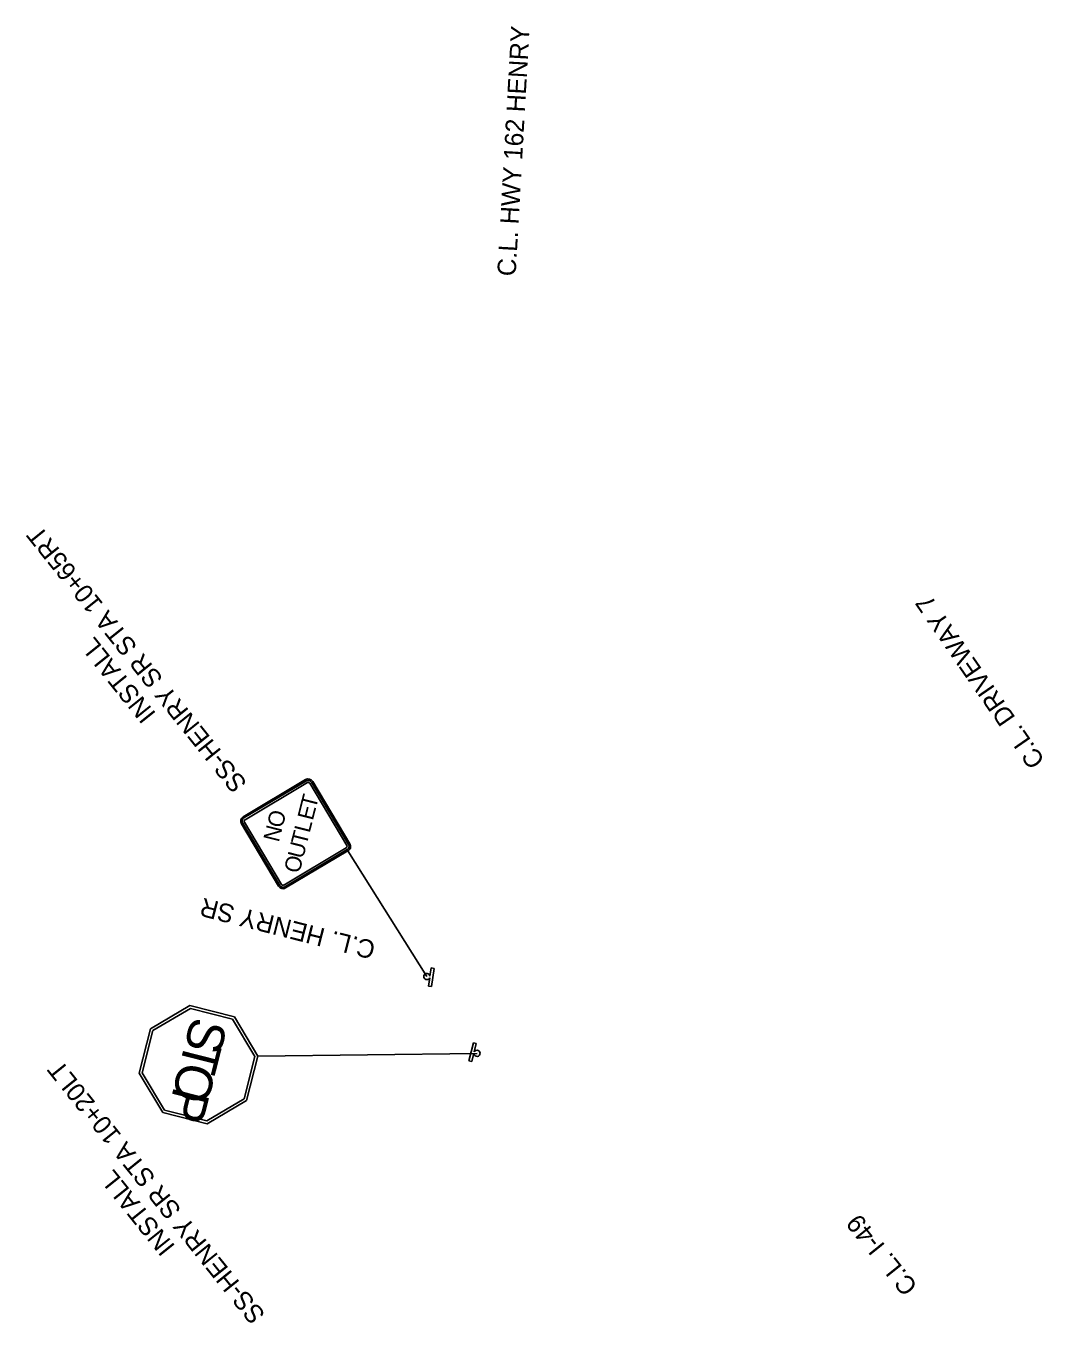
# Model space of a CAD drawing. Extents: x 639753 to 654136, y 407791 to 434220.
# Drawn here: x 651729 to 652391, y 415146 to 415991 of the extents above; entities that cross this region are included whole.
import ezdxf

# ---------------------------------------------------------------- set-up
doc = ezdxf.new("R2010")
doc.units = 0
for name, color, linetype in [('C-TRAF-SYMB', 7, 'Continuous'), ('P_SIGN_SR', 7, 'Continuous'), ('R_Anno_Text', 7, 'Continuous'), ('S_SIGN', 7, 'Continuous')]:
    doc.layers.add(name, color=color, linetype=linetype)

msp = doc.modelspace()

# ---------------------------------------------------------------- linework, layer by layer
at = {"layer": 'C-TRAF-SYMB'}
for p, q in [((652017.93, 415316.73), (652020.88, 415328.36)), ((652020.88, 415328.36), (652022.82, 415327.87)), ((652022.82, 415327.87), (652021.45, 415322.47)), ((652019.86, 415316.24), (652017.93, 415316.73)), ((652021.22, 415321.59), (652019.86, 415316.24)), ((652021.28, 415321.58), (652021.22, 415321.59)), ((652021.45, 415322.47), (652021.49, 415322.46))]:
    msp.add_line(p, q, dxfattribs=at)
for start, end in [(179.59571, 255.73359), (255.73359, 153.41368)]:
    msp.add_arc((652023.28, 415321.56), 2, start, end, dxfattribs=at)
at = {"layer": 'P_SIGN_SR'}
for p, q in [((651939.23, 415453.41), (651990.59, 415371.55)), ((651992.64, 415371.72), (651993.47, 415377.18)), ((651993.47, 415377.18), (651995.45, 415376.87)), ((651995.45, 415376.87), (651993.64, 415365.01)), ((651991.66, 415365.31), (651992.5, 415370.82)), ((651992.5, 415370.82), (651992.46, 415370.83)), ((651992.58, 415371.73), (651992.64, 415371.72)), ((651993.64, 415365.01), (651991.66, 415365.31))]:
    msp.add_line(p, q, dxfattribs=at)
for start, end in [(81.30099, 338.98108), (5.16311, 81.30099)]:
    msp.add_arc((651990.59, 415371.55), 2, start, end, dxfattribs=at)
at = {"layer": 'S_SIGN'}
for p, q in [((651911.64, 415499.83), (651871.02, 415475.68)), ((651940.41, 415458.04), (651916.26, 415498.65)), ((651869.85, 415471.06), (651893.99, 415430.44)), ((651898.62, 415429.26), (651939.23, 415453.41)), ((651836.32, 415352.74), (651810.68, 415337.49)), ((651865.24, 415345.39), (651836.32, 415352.74)), ((651880.48, 415319.74), (651865.24, 415345.39)), ((651810.68, 415337.49), (651803.32, 415308.58)), ((651873.13, 415290.83), (651880.48, 415319.74)), ((651880.48, 415319.74), (652023.28, 415321.56)), ((651803.32, 415308.58), (651818.57, 415282.93)), ((651818.57, 415282.93), (651847.49, 415275.58)), ((651847.49, 415275.58), (651873.13, 415290.83))]:
    msp.add_line(p, q, dxfattribs=at)
for points in [[(651912.12, 415499.02), (651871.5, 415474.88)], [(651872.17, 415473.75), (651912.79, 415497.89)], [(651912.12, 415499.02), (651912.12, 415499.02), (651912.12, 415499.02)], [(651914.33, 415497.5), (651938.48, 415456.89)], [(651939.6, 415457.56), (651915.46, 415498.17)], [(651870.65, 415471.53), (651894.8, 415430.92)], [(651870.65, 415471.53), (651870.65, 415471.53), (651870.65, 415471.53)], [(651895.93, 415431.59), (651871.78, 415472.21)], [(651938.08, 415455.35), (651897.47, 415431.2)], [(651898.14, 415430.07), (651938.75, 415454.22)], [(651939.6, 415457.56), (651939.6, 415457.56), (651939.6, 415457.56)], [(651898.14, 415430.07), (651898.14, 415430.07), (651898.14, 415430.07)], [(651836.32, 415352.74), (651810.68, 415337.49)], [(651812.24, 415336.33), (651836.6, 415350.81)], [(651865.24, 415345.39), (651836.32, 415352.74)], [(651836.32, 415352.74), (651836.32, 415352.74), (651836.32, 415352.74)], [(651836.6, 415350.81), (651864.07, 415343.83)], [(651864.07, 415343.83), (651878.55, 415319.46)], [(651880.48, 415319.74), (651865.24, 415345.39)], [(651865.24, 415345.39), (651865.24, 415345.39), (651865.24, 415345.39)], [(651810.68, 415337.49), (651803.32, 415308.58)], [(651805.25, 415308.86), (651812.24, 415336.33)], [(651810.68, 415337.49), (651810.68, 415337.49), (651810.68, 415337.49)], [(651878.55, 415319.46), (651871.57, 415291.99)], [(651873.13, 415290.83), (651880.48, 415319.74)], [(651880.48, 415319.74), (651880.48, 415319.74), (651880.48, 415319.74)], [(651803.32, 415308.58), (651818.57, 415282.93)], [(651803.32, 415308.58), (651803.32, 415308.58), (651803.32, 415308.58)], [(651819.74, 415284.5), (651805.25, 415308.86)], [(651871.57, 415291.99), (651847.21, 415277.51)], [(651818.57, 415282.93), (651847.49, 415275.58)], [(651818.57, 415282.93), (651818.57, 415282.93), (651818.57, 415282.93)], [(651847.21, 415277.51), (651819.74, 415284.5)], [(651847.49, 415275.58), (651873.13, 415290.83)], [(651873.13, 415290.83), (651873.13, 415290.83), (651873.13, 415290.83)], [(651847.49, 415275.58), (651847.49, 415275.58), (651847.49, 415275.58)]]:
    msp.add_lwpolyline(points, dxfattribs=at)
for centre, radius, start, end in [((651913.36, 415496.93), 3.37, 30.73287, 120.7325), ((651913.36, 415496.93), 2.44, 30.73287, 120.7325), ((651913.36, 415496.93), 1.12, 30.73287, 120.7325), ((651872.75, 415472.78), 3.37, 120.73269, 210.73245), ((651872.75, 415472.78), 2.44, 120.73269, 210.73245), ((651872.75, 415472.78), 1.12, 120.73269, 210.73245), ((651937.51, 415456.31), 1.12, 300.73266, 30.73287), ((651937.51, 415456.31), 2.44, 300.73266, 30.73287), ((651937.51, 415456.31), 3.37, 300.73266, 30.73287), ((651896.89, 415432.17), 3.37, 210.73245, 300.73266), ((651896.89, 415432.17), 2.44, 210.73245, 300.73266), ((651896.89, 415432.17), 1.12, 210.73245, 300.73266)]:
    msp.add_arc(centre, radius, start, end, dxfattribs=at)

# ---------------------------------------------------------------- texts
at = {"layer": 'R_Anno_Text'}
for s, rotation, p in [('C.L. HWY 162 HENRY', 86.78041, (652048.39, 415827.44)), ('SS-HENRY SR STA 10+65RT', 128.75345, (651873.98, 415497.53)), ('C.L. DRIVEWAY 7', 124.66748, (652393.58, 415512.28)), ('INSTALL', 128.75345, (651814.63, 415542.72)), ('C.L. HENRY SR', 165.73457, (651957.92, 415394.21)), ('SS-HENRY SR STA 10+20LT', 128.75345, (651885.88, 415151.51)), ('INSTALL', 128.75345, (651827.17, 415195.9)), ('C.L. I-49', 128.75345, (652310.79, 415169.9))]:
    msp.add_text(s, height=12, rotation=rotation, dxfattribs=at).set_placement(p)
at = {"layer": 'S_SIGN'}
for s, height, rotation, p in [('T', 10.5, 75.7327, (651918.22, 415480.26)), ('O', 10.5, 75.7327, (651896.48, 415467.83)), ('E', 10.5, 75.7327, (651916.32, 415472.79)), ('N', 10.5, 75.7327, (651894.14, 415458.63)), ('L', 10.5, 75.7327, (651914.25, 415464.68)), ('T', 10.5, 75.7327, (651912.19, 415456.57)), ('U', 10.5, 75.7327, (651909.97, 415447.83)), ('O', 10.5, 75.7327, (651907.54, 415438.29)), ('S', 24.01, 255.73359, (651837.67, 415346.21)), ('T', 24.01, 255.73359, (651833.83, 415331.13)), ('O', 24.01, 255.73359, (651830.27, 415317.14)), ('P', 24.01, 255.73359, (651826.11, 415300.75))]:
    msp.add_text(s, height=height, rotation=rotation, dxfattribs=at).set_placement(p)

doc.saveas('drawing.dxf')
